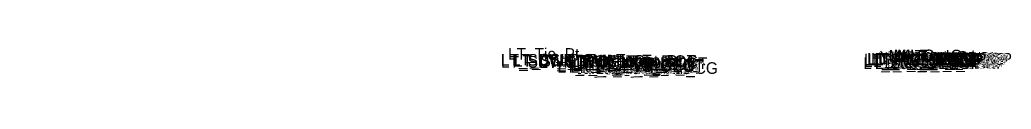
# Model space of a CAD drawing. Extents: x -26 to 4229, y -10 to 9523.
# Drawn here: x 3000 to 3171.5, y 2000 to 2005.9 of the extents above; entities that cross this region are included whole.
import ezdxf

# ---------------------------------------------------------------- set-up
doc = ezdxf.new("R2010")
doc.units = 0
doc.layers.add('Default', color=7, linetype='Continuous')

msp = doc.modelspace()

# ---------------------------------------------------------------- texts
at = {"layer": 'Default'}
for s, height, p in [('LT_Tie_Pt', 2, (3084.47, 2003.76)), ('MI_Top In', 2, (3150.36, 2003.44)), ('MI_Top Out', 2, (3151.22, 2003.48)), ('MI_Crown', 2, (3151.82, 2003.51)), ('LT_SDWK_Out_Top', 2, (3083.24, 2002.75)), ('LT_SDWK_Out_Bot', 2, (3083.27, 2002.41)), ('LT_CSLP_Pnt', 2, (3085.17, 2002.77)), ('LT_Sub_Trench_Out_DLT', 2, (3085.49, 2002.57)), ('LT_SDWK_In_Top', 2, (3089.86, 2002.65)), ('LT_SDWK_In_Bot', 2, (3089.89, 2002.31)), ('LT_CG_Top_Face', 2, (3094.76, 2002.53)), ('LT_CG_Top_BOC', 2, (3095.28, 2002.53)), ('LT_CG_Top_Gut', 2, (3095.74, 2002.03)), ('LT_PV2_OEOT', 2, (3099.67, 2001.9)), ('LT_PV3_OEOT', 2, (3099.67, 2001.65)), ('LT_PV1_OEOT', 2, (3100.24, 2002.15)), ('LT_Sub_OEEOP', 2, (3145.96, 2002.15)), ('LT_PV2_OEEOP', 2, (3146.06, 2002.78)), ('LT_PV3_OEEOP', 2, (3146.06, 2002.53)), ('LT_PV1_OEEOP', 2, (3146.62, 2002.9)), ('LT_PV2_IEEOP', 2, (3146.7, 2002.78)), ('LT_PV1_IEEOP', 2, (3147.27, 2002.9)), ('LT_PV2_PGL1', 2, (3147.63, 2002.78)), ('LT_PV3_PGL1', 2, (3147.63, 2002.53)), ('LT_PV2_PGL', 2, (3147.96, 2002.78)), ('LT_PV4_PGL', 2, (3147.96, 2002.15)), ('LT_PV1_PGL', 2, (3148.53, 2003.03)), ('MI_Face In', 2, (3148.65, 2003.19)), ('MI_Bot In', 2, (3149.63, 2003.03)), ('RT_Sub_OEEOP', 2, (3149.92, 2002.19)), ('RT_PV2_OEEOP', 2, (3150.01, 2002.82)), ('RT_PV3_OEEOP', 2, (3150.01, 2002.57)), ('RT_PV1_OEEOP', 2, (3150.58, 2002.94)), ('RT_PV2_IEEOP', 2, (3150.66, 2002.82)), ('MI_Face Out', 2, (3151.01, 2003.23)), ('RT_PV1_IEEOP', 2, (3151.22, 2002.94)), ('RT_PV2_PGL1', 2, (3151.58, 2002.82)), ('RT_PV3_PGL1', 2, (3151.58, 2002.57)), ('RT_PV2_PGL', 2, (3151.92, 2002.82)), ('RT_PV4_PGL', 2, (3151.92, 2002.19)), ('MI_Bot Out', 2, (3152.01, 2003.07)), ('RT_PV1_PGL', 2, (3152.48, 2003.07)), ('LT_CG1_Shelf_Out', 2, (3093.05, 2001.51)), ('LT_CG_Bot_BOC', 2, (3095.31, 2001.52)), ('LT_Sub_OEOP', 2, (3096.36, 2001.25)), ('LT_Sub_OEOT_CG', 2, (3096.87, 2001.32)), ('LT_CG_Bot_IE', 2, (3099.41, 2001.57)), ('LT_Sub_OEOT', 2, (3099.58, 2001.28)), ('-', 0.0001, (3000, 2000)), ('-', 0.0001, (3000, 2000)), ('-', 0.0001, (3000, 2000)), ('-', 0.0001, (3000, 2000)), ('-', 0.0001, (3000, 2000)), ('-', 0.0001, (3000, 2000)), ('-', 0.0001, (3000, 2000))]:
    msp.add_text(s, height=height, dxfattribs=at).set_placement(p)

doc.saveas('drawing.dxf')
